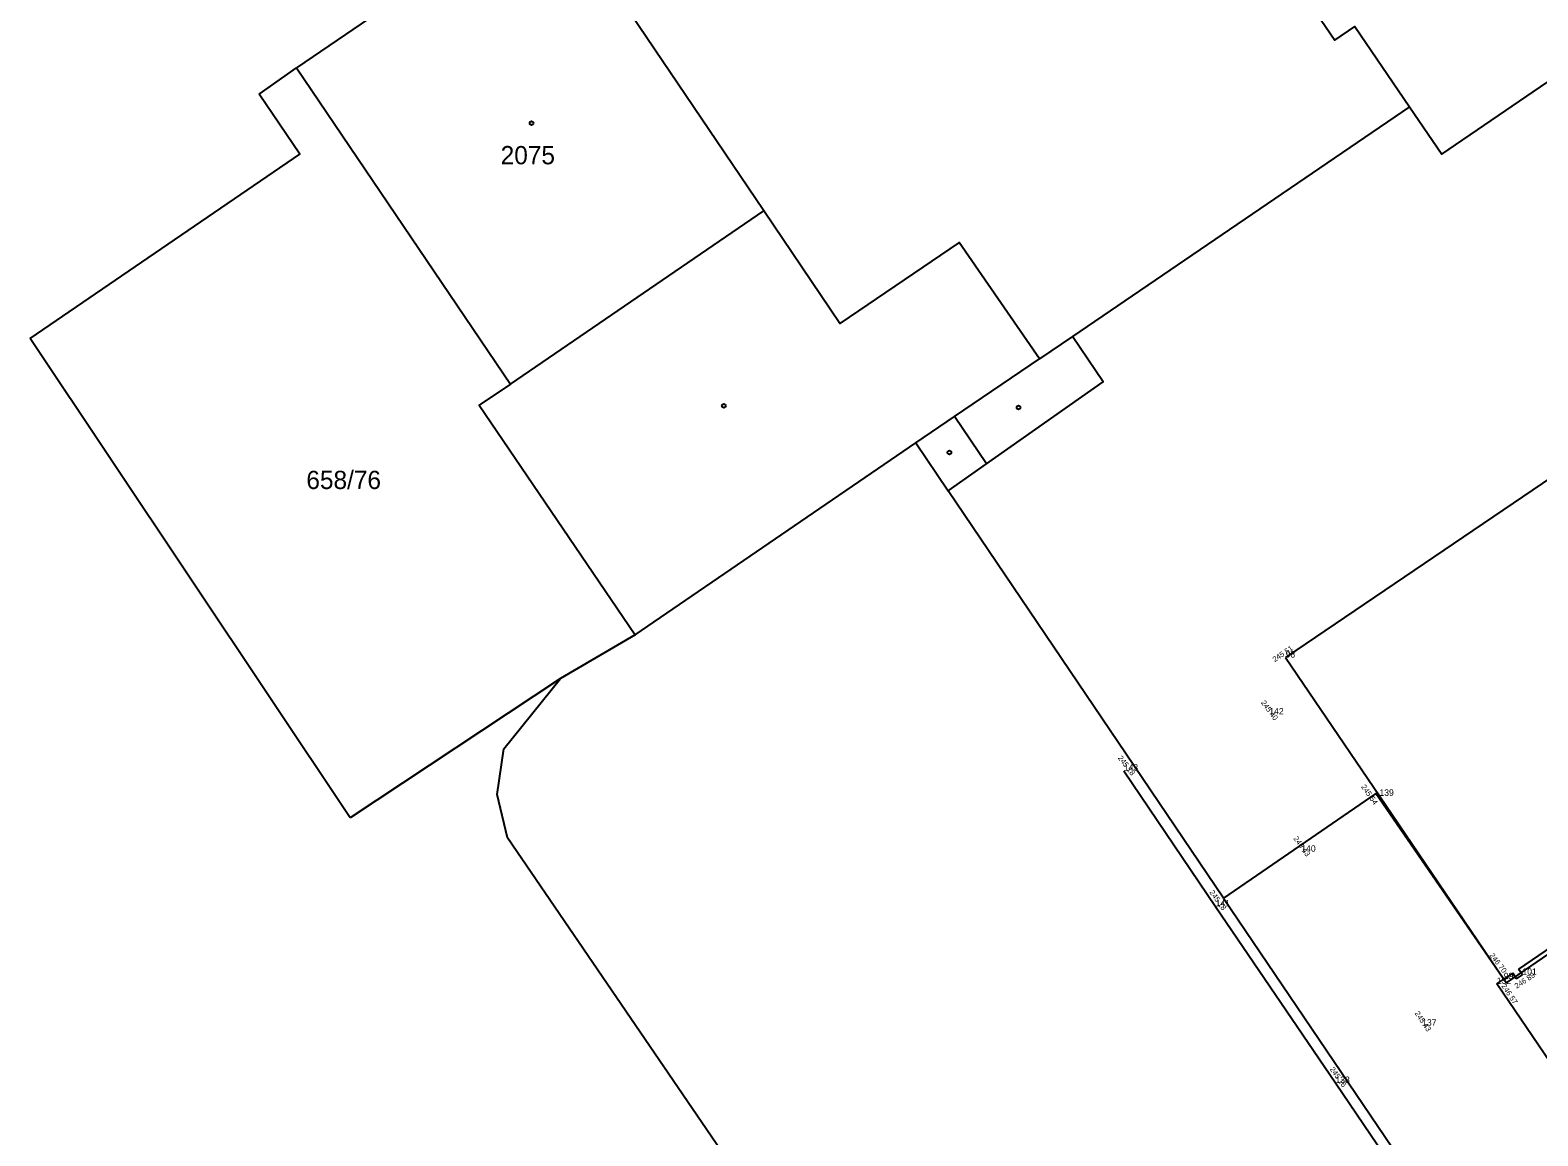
# Model space of a CAD drawing. Extents: x -675895 to -675697, y -1071173 to -1070976.
# Drawn here: x -675895.1 to -675824.8, y -1071068.6 to -1071017.1 of the extents above; entities that cross this region are included whole.
import ezdxf

# ---------------------------------------------------------------- set-up
doc = ezdxf.new("R2010")
doc.units = 0
for name, color, linetype in [('Vrstva 1', 7, 'Continuous'), ('Vrstva 2', 7, 'Continuous'), ('Vrstva 3', 7, 'Continuous'), ('Vrstva 4', 7, 'Continuous'), ('Vrstva 50', 7, 'Continuous'), ('Vrstva 6', 7, 'Continuous')]:
    doc.layers.add(name, color=color, linetype=linetype)

msp = doc.modelspace()

# ---------------------------------------------------------------- linework, layer by layer
at = {"layer": 'Vrstva 1'}
for p, q in [((-675836.59, -1071046.32), (-675836.59, -1071046.32)), ((-675837.35, -1071048.97), (-675837.35, -1071048.97)), ((-675844.13, -1071051.59), (-675844.13, -1071051.59)), ((-675832.22, -1071052.76), (-675832.22, -1071052.76)), ((-675835.86, -1071055.36), (-675835.86, -1071055.36)), ((-675839.85, -1071057.91), (-675839.85, -1071057.91)), ((-675826.75, -1071061.52), (-675826.75, -1071061.52)), ((-675826.43, -1071061.3), (-675826.43, -1071061.3)), ((-675825.56, -1071061.09), (-675825.56, -1071061.09)), ((-675830.23, -1071063.46), (-675830.23, -1071063.46)), ((-675834.27, -1071066.13), (-675834.27, -1071066.13))]:
    msp.add_line(p, q, dxfattribs=at)
at = {"layer": 'Vrstva 4'}
msp.add_line((-675826.75, -1071061.52), (-675826.43, -1071061.3), dxfattribs=at)
for points in [[(-675844.13, -1071051.59), (-675839.85, -1071057.91), (-675834.27, -1071066.13), (-675826.06, -1071078.25), (-675815.62, -1071093.57), (-675806.37, -1071107.19)], [(-675801.49, -1071098.68), (-675826.75, -1071061.52)]]:
    msp.add_lwpolyline(points, dxfattribs=at)
at = {"layer": 'Vrstva 50'}
for p, q in [((-675873.21, -1071012.43), (-675882.67, -1071018.86)), ((-675884.41, -1071020.09), (-675882.67, -1071018.86)), ((-675830.82, -1071020.68), (-675846.52, -1071031.37)), ((-675872.7, -1071033.59), (-675860.89, -1071025.52)), ((-675880.17, -1071053.79), (-675895.07, -1071031.46)), ((-675852.01, -1071035.1), (-675848.05, -1071032.41)), ((-675853.82, -1071036.33), (-675852.01, -1071035.1)), ((-675850.52, -1071037.3), (-675852.01, -1071035.1)), ((-675839.48, -1071057.52), (-675852.31, -1071038.56)), ((-675866.89, -1071045.26), (-675870.37, -1071047.29)), ((-675870.37, -1071047.29), (-675880.17, -1071053.79))]:
    msp.add_line(p, q, dxfattribs=at)
for points in [[(-675822.08, -1071017.95), (-675822.7, -1071017.04), (-675814.81, -1071011.69), (-675818.28, -1071006.58), (-675817.83, -1071006.27), (-675822.48, -1070999.41), (-675838.87, -1071010.86), (-675834.3, -1071017.57), (-675833.36, -1071016.94), (-675830.82, -1071020.68)], [(-675846.52, -1071031.37), (-675848.05, -1071032.41), (-675851.8, -1071027), (-675857.35, -1071030.76), (-675860.89, -1071025.52), (-675869.27, -1071013.13), (-675868.53, -1071012.63), (-675869.93, -1071010.56), (-675871.96, -1071011.94), (-675872.13, -1071011.69)], [(-675830.82, -1071020.68), (-675829.32, -1071022.88), (-675822.08, -1071017.95)], [(-675882.67, -1071018.86), (-675872.7, -1071033.59), (-675874.15, -1071034.57), (-675866.89, -1071045.26)], [(-675895.07, -1071031.46), (-675882.51, -1071022.89), (-675884.41, -1071020.09)], [(-675852.31, -1071038.56), (-675850.52, -1071037.3), (-675845.09, -1071033.48), (-675846.52, -1071031.37)], [(-675866.89, -1071045.26), (-675853.82, -1071036.33), (-675852.31, -1071038.56)], [(-675860.91, -1071072.17), (-675872.83, -1071054.71), (-675873.32, -1071052.7), (-675873.01, -1071050.57), (-675870.37, -1071047.29)], [(-675794.05, -1071059.25), (-675801.81, -1071064.57), (-675811.09, -1071051.03), (-675826.32, -1071061.47), (-675832.38, -1071052.65), (-675839.48, -1071057.52)], [(-675839.48, -1071057.52), (-675805.95, -1071107.05), (-675812.04, -1071111.17), (-675806.1, -1071120.13), (-675804.7, -1071122.14), (-675803.11, -1071124.51), (-675804.1, -1071125.34)]]:
    msp.add_lwpolyline(points, dxfattribs=at)
for centre in [(-675871.713, -1071021.44), (-675862.758, -1071034.6), (-675849.028, -1071034.68), (-675852.253, -1071036.775)]:
    msp.add_circle(centre, 0.0875, dxfattribs=at)
at = {"layer": 'Vrstva 6'}
for p, q in [((-675821, -1071035.75), (-675836.59, -1071046.32)), ((-675823.058, -1071058.994), (-675825.74, -1071060.828)), ((-675825.56, -1071061.09), (-675825.74, -1071060.828)), ((-675826.011, -1071061.013), (-675826.43, -1071061.3)), ((-675825.834, -1071061.275), (-675826.011, -1071061.013)), ((-675825.834, -1071061.275), (-675825.56, -1071061.09))]:
    msp.add_line(p, q, dxfattribs=at)
msp.add_lwpolyline([(-675836.59, -1071046.32), (-675832.22, -1071052.76), (-675826.43, -1071061.3)], dxfattribs=at)

# ---------------------------------------------------------------- texts
at = {"layer": 'Vrstva 2'}
for s, p in [('98', (-675836.59, -1071046.32)), ('142', (-675837.35, -1071048.97)), ('143', (-675844.13, -1071051.59)), ('139', (-675832.22, -1071052.76)), ('140', (-675835.86, -1071055.36)), ('141', (-675839.85, -1071057.91)), ('99', (-675826.43, -1071061.3)), ('101', (-675825.56, -1071061.09)), ('132', (-675826.75, -1071061.52)), ('137', (-675830.23, -1071063.46)), ('138', (-675834.27, -1071066.13))]:
    msp.add_text(s, height=0.3, dxfattribs=at).set_placement(p)
at = {"layer": 'Vrstva 3'}
for s, rotation, p in [('245 51 ', 33.9954, (-675837.093, -1071046.54)), ('245 40 ', 306.50144, (-675837.752, -1071048.424)), ('245 18 ', 307.48356, (-675844.419, -1071051.002)), ('245 54 ', 305.20713, (-675833.085, -1071052.341)), ('245 43 ', 305.29761, (-675836.238, -1071054.75)), ('245 18 ', 305.88214, (-675840.152, -1071057.262)), ('246 70 ', 307.56859, (-675827.105, -1071060.196)), ('246 57 ', 303.57444, (-675826.553, -1071061.614)), ('246 89 ', 33.24333, (-675825.826, -1071061.748)), ('245 43 ', 304.28688, (-675830.589, -1071062.891)), ('245 16 ', 305.11201, (-675834.545, -1071065.493))]:
    msp.add_text(s, height=0.25, rotation=rotation, dxfattribs=at).set_placement(p)
at = {"layer": 'Vrstva 50'}
for s, p in [('2075', (-675873.152, -1071023.354)), ('658/76', (-675882.204, -1071038.475))]:
    msp.add_text(s, height=0.85, dxfattribs=at).set_placement(p)

doc.saveas('drawing.dxf')
